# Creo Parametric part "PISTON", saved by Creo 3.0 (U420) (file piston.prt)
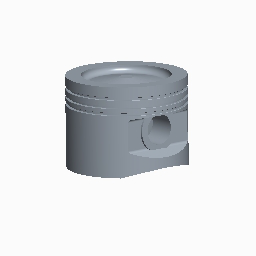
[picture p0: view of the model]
Units: millimeter Kilogram Sec (mmKs); MM, KILOGRAM, SECS

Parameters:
  MATERIAL = "ST37"

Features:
  1. datum plane "RIGHT"
  2. datum plane "TOP"
  3. datum plane "FRONT"
  4. coordinate system
  5. protrusion
  6. cut
  7. round
  8. datum plane "DTM2", "PIN_PLN"
  9. datum axis "A_14"
  10. extrusion "Extrude 9"
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
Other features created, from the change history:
  extrusion "Extrude 10" (2 times)
  round "Round 15"
  round "Round 16"
  round "Round 17"
  round "Round 18"
  mirror "Mirror 4"
  extrusion "Extrude 9 (2)"
  round "Round 7"
  round "Round 8"
  mirror "Mirror 5"
  extrusion "Extrude 10 (2)"
  round "Round 9"
  round "Round 10"
  round "Round 11"
  mirror "Mirror 6"
  extrusion "Extrude 8 (2)"
  sketch "Sketch 1"
  revolved cut "Revolve 2"
  sketch "Sketch 2"
  extruded cut "Extrude 11"
  sketch "Sketch 3"

Other named items: TOP_CUT, BOTTOM_CUT, RING, PIN_AXIS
